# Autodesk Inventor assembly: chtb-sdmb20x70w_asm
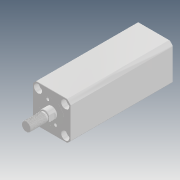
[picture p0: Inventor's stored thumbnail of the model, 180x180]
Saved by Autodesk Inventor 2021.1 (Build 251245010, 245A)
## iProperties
Company: Microsoft
Created: 2018-05
Part Number: chtb-sdmb20x70w_asm
Description: STEP AP214
Document SubType Name: Assembly
Designer: user
Title: chtb-sdmb20x70w_asm.STEP
Author: Windows
Revision Number: ÈÎºÎ
Sending System: SolidWorks 2015
Preprocessor: SwSTEP 2.0
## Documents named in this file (4)
- D:\Vault_2016\Projekty\Clamptek\Hydraulic\CHTB\CHTB-20\Inventor\CHTB-SDMB20x70W\chtb-sdmb20x70w_asm.iam
- D:\Vault_2016\Projekty\Clamptek\Hydraulic\CHTB\CHTB-20\Inventor\CHTB-SDMB20x70W\CHTB-SDMB20X70NBT.ipt
- D:\Vault_2016\Projekty\Clamptek\Hydraulic\CHTB\CHTB-20\Inventor\CHTB-SDMB20x70W\CHTB-SDMB20X70WHSG.ipt
- D:\Vault_2016\Projekty\Clamptek\Hydraulic\CHTB\CHTB-20\Inventor\CHTB-SDMB20x70W\QG_3.ipt
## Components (3 placed, 3 different names)
1. CHTB-SDMB20X70NBT_1
2. CHTB-SDMB20X70WHSG_2
3. QG_3_3
